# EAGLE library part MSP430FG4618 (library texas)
MIXED SIGNAL MICROCONTROLLER Auto generated by make-symbol-device-package-bsdl.ulp Rev. 19 Source: http://focus.ti.com/docs/prod/folders/print/msp430fg4618.html
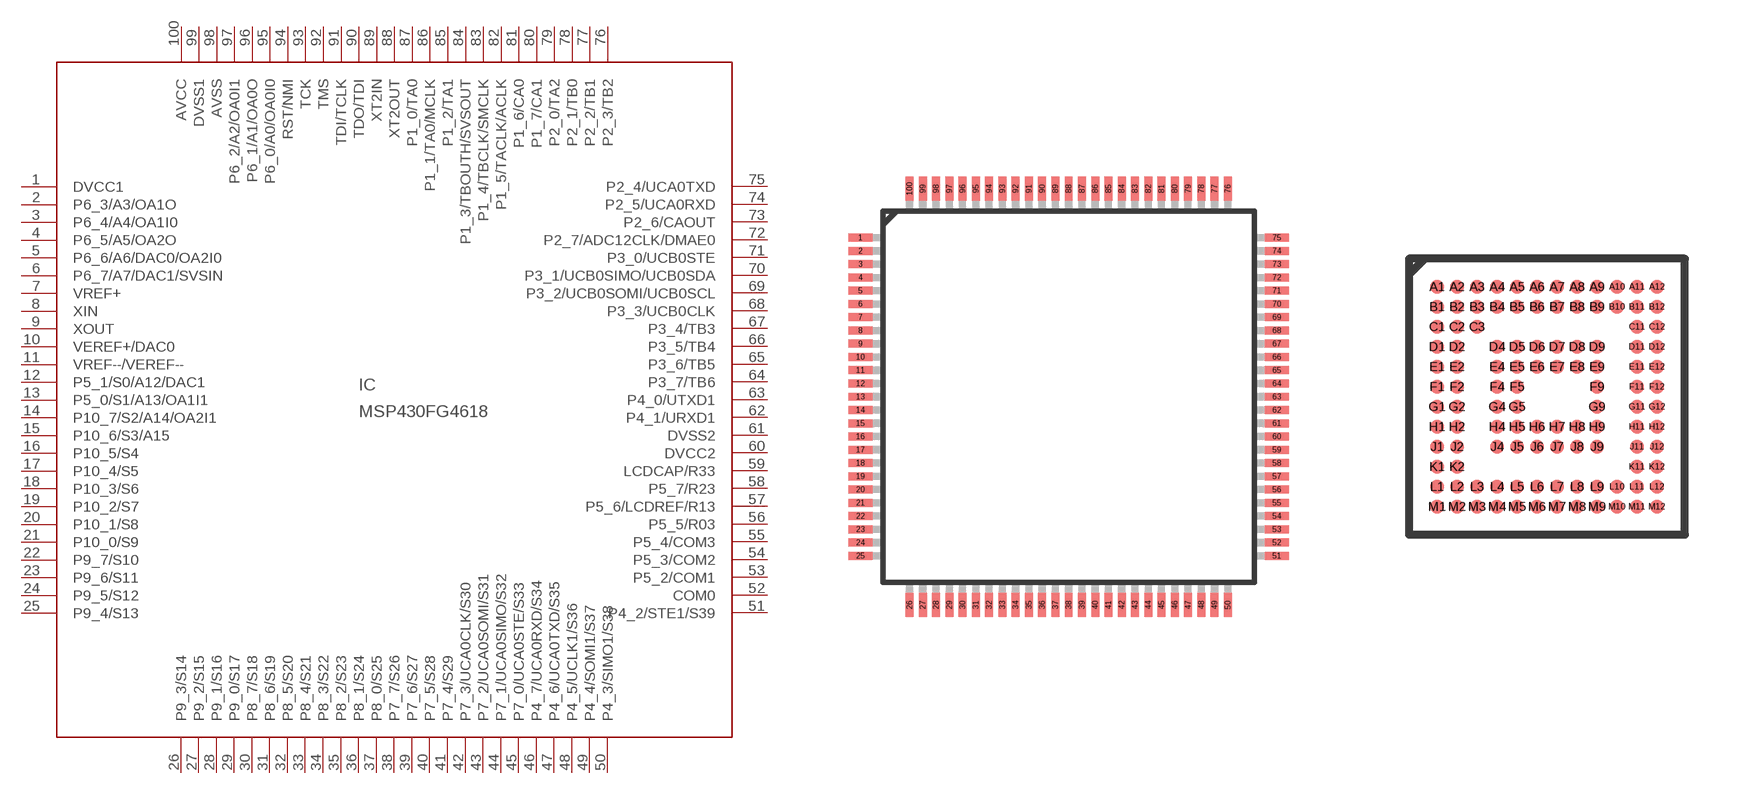
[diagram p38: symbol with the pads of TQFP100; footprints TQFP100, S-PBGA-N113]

Designator prefix IC

## MSP430FG4618PZ (MPN: MSP430FG4618IPZ; OC_FARNELL: 1470488; OC_NEWARK: 22M1151)  [TQFP100]
1  DVCC1  pwr
2  P6_3/A3/OA1O
3  P6_4/A4/OA1I0
4  P6_5/A5/OA2O
5  P6_6/A6/DAC0/OA2I0
6  P6_7/A7/DAC1/SVSIN
7  VREF+  out
8  XIN  in
9  XOUT  out
10  VEREF+/DAC0
11  VREF--/VEREF--  in
12  P5_1/S0/A12/DAC1
13  P5_0/S1/A13/OA1I1
14  P10_7/S2/A14/OA2I1
15  P10_6/S3/A15
16  P10_5/S4
17  P10_4/S5
18  P10_3/S6
19  P10_2/S7
20  P10_1/S8
21  P10_0/S9
22  P9_7/S10
23  P9_6/S11
24  P9_5/S12
25  P9_4/S13
26  P9_3/S14
27  P9_2/S15
28  P9_1/S16
29  P9_0/S17
30  P8_7/S18
31  P8_6/S19
32  P8_5/S20
33  P8_4/S21
34  P8_3/S22
35  P8_2/S23
36  P8_1/S24
37  P8_0/S25
38  P7_7/S26
39  P7_6/S27
40  P7_5/S28
41  P7_4/S29
42  P7_3/UCA0CLK/S30
43  P7_2/UCA0SOMI/S31
44  P7_1/UCA0SIMO/S32
45  P7_0/UCA0STE/S33
46  P4_7/UCA0RXD/S34
47  P4_6/UCA0TXD/S35
48  P4_5/UCLK1/S36
49  P4_4/SOMI1/S37
50  P4_3/SIMO1/S38
51  P4_2/STE1/S39
52  COM0  out
53  P5_2/COM1
54  P5_3/COM2
55  P5_4/COM3
56  P5_5/R03
57  P5_6/LCDREF/R13
58  P5_7/R23
59  LCDCAP/R33  in
60  DVCC2  pwr
61  DVSS2  pwr
62  P4_1/URXD1
63  P4_0/UTXD1
64  P3_7/TB6
65  P3_6/TB5
66  P3_5/TB4
67  P3_4/TB3
68  P3_3/UCB0CLK
69  P3_2/UCB0SOMI/UCB0SCL
70  P3_1/UCB0SIMO/UCB0SDA
71  P3_0/UCB0STE
72  P2_7/ADC12CLK/DMAE0
73  P2_6/CAOUT
74  P2_5/UCA0RXD
75  P2_4/UCA0TXD
76  P2_3/TB2
77  P2_2/TB1
78  P2_1/TB0
79  P2_0/TA2
80  P1_7/CA1
81  P1_6/CA0
82  P1_5/TACLK/ACLK
83  P1_4/TBCLK/SMCLK
84  P1_3/TBOUTH/SVSOUT
85  P1_2/TA1
86  P1_1/TA0/MCLK
87  P1_0/TA0
88  XT2OUT  out
89  XT2IN  in
90  TDO/TDI
91  TDI/TCLK  in
92  TMS  in
93  TCK  in
94  RST/NMI  in
95  P6_0/A0/OA0I0
96  P6_1/A1/OA0O
97  P6_2/A2/OA0I1
98  AVSS  pwr
99  DVSS1  pwr
100  AVCC  pwr

## MSP430FG4618ZQW (MPN: MSP430FG4618IZQW; OC_FARNELL: unknown; OC_NEWARK: 61M7852)  [S-PBGA-N113]
A1  DVCC1  pwr
A2  AVCC  pwr
A3  AVSS  pwr
A4  P6_0/A0/OA0I0
A5  TCK  in
A6  TDO/TDI
A7  P1_0/TA0
A8  P1_3/TBOUTH/SVSOUT
A9  P1_6/CA0
A10  P2_0/TA2
A11  P2_3/TB2
B1  P6_3/A3/OA1O
B2  P6_4/A4/OA1I0
B3  DVSS1  pwr
B4  P6_2/A2/OA0I1
B5  RST/NMI  in
B6  XT2IN  in
B7  XT2OUT  out
B8  P1_4/TBCLK/SMCLK
B9  P1_5/TACLK/ACLK
B10  P1_7/CA1
B12  P2_4/UCA0TXD
C1  P6_6/A6/DAC0/OA2I0
C2  P6_5/A5/OA2O
C3  P6_7/A7/DAC1/SVSIN
C11  P2_5/UCA0RXD
C12  P2_6/CAOUT
D1  XIN  in
D2  VREF+  out
D5  P6_1/A1/OA0O
D6  TDI/TCLK  in
D7  P1_2/TA1
D8  P2_1/TB0
D11  P3_0/UCB0STE
D12  P3_1/UCB0SIMO/UCB0SDA
E1  XOUT  out
E2  VEREF+/DAC0
E4  VREF--/VEREF--  in
E5  P10_7/S2/A14/OA2I1
E6  TMS  in
E7  P1_1/TA0/MCLK
E8  P2_2/TB1
E9  P2_7/ADC12CLK/DMAE0
E11  P3_3/UCB0CLK
E12  P3_4/TB3
F1  P5_1/S0/A12/DAC1
F2  P5_0/S1/A13/OA1I1
F4  P10_4/S5
F5  P10_1/S8
F9  P3_2/UCB0SOMI/UCB0SCL
F11  P3_6/TB5
F12  P3_7/TB6
G1  P10_6/S3/A15
G2  P10_5/S4
G4  P9_6/S11
G5  P8_4/S21
G9  P3_5/TB4
G11  P4_1/URXD1
G12  DVSS2  pwr
H1  P10_3/S6
H2  P10_2/S7
H4  P8_7/S18
H5  P8_1/S24
H6  P7_3/UCA0CLK/S30
H7  P4_4/SOMI1/S37
H9  P4_0/UTXD1
H11  LCDCAP/R33  in
H12  DVCC2  pwr
J1  P10_0/S9
J2  P9_7/S10
J5  P8_0/S25
J6  P7_5/S28
J7  P4_7/UCA0RXD/S34
J8  P5_3/COM2
J11  P5_7/R23
J12  P5_6/LCDREF/R13
K1  P9_5/S12
K2  P9_2/S15
K11  P5_5/R03
K12  P5_4/COM3
L1  P9_4/S13
L3  P9_1/S16
L4  P8_6/S19
L5  P8_3/S22
L6  P7_6/S27
L7  P7_2/UCA0SOMI/S31
L8  P7_0/UCA0STE/S33
L9  P4_5/UCLK1/S36
L10  COM0  out
L12  P5_2/COM1
M2  P9_3/S14
M3  P9_0/S17
M4  P8_5/S20
M5  P8_2/S23
M6  P7_7/S26
M7  P7_4/S29
M8  P7_1/UCA0SIMO/S32
M9  P4_6/UCA0TXD/S35
M10  P4_3/SIMO1/S38
M11  P4_2/STE1/S39

## Footprint TQFP100 (pad centres in mm)
PLASTIC 100-PIN TQFP (PZ) Auto generated by make-symbol-device-package-bsdl.ulp Rev. 19 Source: http://focus.ti.com/docs/prod/folders/print/msp430fg4618.html
smd 0.9 x 0.3: 1 -7.85,6; 2 -7.85,5.5; 3 -7.85,5; 4 -7.85,4.5; 5 -7.85,4; 6 -7.85,3.5; 7 -7.85,3; 8 -7.85,2.5; 9 -7.85,2; 10 -7.85,1.5; 11 -7.85,1; 12 -7.85,0.5; 13 -7.85,0; 14 -7.85,-0.5; 15 -7.85,-1; 16 -7.85,-1.5; 17 -7.85,-2; 18 -7.85,-2.5; 19 -7.85,-3; 20 -7.85,-3.5; 21 -7.85,-4; 22 -7.85,-4.5; 23 -7.85,-5; 24 -7.85,-5.5; 25 -7.85,-6; 51 7.85,-6; 52 7.85,-5.5; 53 7.85,-5; 54 7.85,-4.5; 55 7.85,-4; 56 7.85,-3.5; 57 7.85,-3; 58 7.85,-2.5; 59 7.85,-2; 60 7.85,-1.5; 61 7.85,-1; 62 7.85,-0.5; 63 7.85,0; 64 7.85,0.5; 65 7.85,1; 66 7.85,1.5; 67 7.85,2; 68 7.85,2.5; 69 7.85,3; 70 7.85,3.5; 71 7.85,4; 72 7.85,4.5; 73 7.85,5; 74 7.85,5.5; 75 7.85,6
smd 0.3 x 0.9: 26 -6,-7.85; 27 -5.5,-7.85; 28 -5,-7.85; 29 -4.5,-7.85; 30 -4,-7.85; 31 -3.5,-7.85; 32 -3,-7.85; 33 -2.5,-7.85; 34 -2,-7.85; 35 -1.5,-7.85; 36 -1,-7.85; 37 -0.5,-7.85; 38 0,-7.85; 39 0.5,-7.85; 40 1,-7.85; 41 1.5,-7.85; 42 2,-7.85; 43 2.5,-7.85; 44 3,-7.85; 45 3.5,-7.85; 46 4,-7.85; 47 4.5,-7.85; 48 5,-7.85; 49 5.5,-7.85; 50 6,-7.85; 76 6,7.85; 77 5.5,7.85; 78 5,7.85; 79 4.5,7.85; 80 4,7.85; 81 3.5,7.85; 82 3,7.85; 83 2.5,7.85; 84 2,7.85; 85 1.5,7.85; 86 1,7.85; 87 0.5,7.85; 88 0,7.85; 89 -0.5,7.85; 90 -1,7.85; 91 -1.5,7.85; 92 -2,7.85; 93 -2.5,7.85; 94 -3,7.85; 95 -3.5,7.85; 96 -4,7.85; 97 -4.5,7.85; 98 -5,7.85; 99 -5.5,7.85; 100 -6,7.85

## Footprint S-PBGA-N113 (pad centres in mm)
PLASTIC BGA 113-BALL (ZQW) Auto generated by make-symbol-device-package-bsdl.ulp Rev. 19 Source: http://focus.ti.com/docs/prod/folders/print/msp430fg4618.html
smd 0.35 x 0.35: A1 -2.75,2.75; A2 -2.25,2.75; A3 -1.75,2.75; A4 -1.25,2.75; A5 -0.75,2.75; A6 -0.25,2.75; A7 0.25,2.75; A8 0.75,2.75; A9 1.25,2.75; A10 1.75,2.75; A11 2.25,2.75; A12 2.75,2.75; B1 -2.75,2.25; B2 -2.25,2.25; B3 -1.75,2.25; B4 -1.25,2.25; B5 -0.75,2.25; B6 -0.25,2.25; B7 0.25,2.25; B8 0.75,2.25; B9 1.25,2.25; B10 1.75,2.25; B11 2.25,2.25; B12 2.75,2.25; C1 -2.75,1.75; C2 -2.25,1.75; C3 -1.75,1.75; C11 2.25,1.75; C12 2.75,1.75; D1 -2.75,1.25; D2 -2.25,1.25; D4 -1.25,1.25; D5 -0.75,1.25; D6 -0.25,1.25; D7 0.25,1.25; D8 0.75,1.25; D9 1.25,1.25; D11 2.25,1.25; D12 2.75,1.25; E1 -2.75,0.75; E2 -2.25,0.75; E4 -1.25,0.75; E5 -0.75,0.75; E6 -0.25,0.75; E7 0.25,0.75; E8 0.75,0.75; E9 1.25,0.75; E11 2.25,0.75; E12 2.75,0.75; F1 -2.75,0.25; F2 -2.25,0.25; F4 -1.25,0.25; F5 -0.75,0.25; F9 1.25,0.25; F11 2.25,0.25; F12 2.75,0.25; G1 -2.75,-0.25; G2 -2.25,-0.25; G4 -1.25,-0.25; G5 -0.75,-0.25; G9 1.25,-0.25; G11 2.25,-0.25; G12 2.75,-0.25; H1 -2.75,-0.75; H2 -2.25,-0.75; H4 -1.25,-0.75; H5 -0.75,-0.75; H6 -0.25,-0.75; H7 0.25,-0.75; H8 0.75,-0.75; H9 1.25,-0.75; H11 2.25,-0.75; H12 2.75,-0.75; J1 -2.75,-1.25; J2 -2.25,-1.25; J4 -1.25,-1.25; J5 -0.75,-1.25; J6 -0.25,-1.25; J7 0.25,-1.25; J8 0.75,-1.25; J9 1.25,-1.25; J11 2.25,-1.25; J12 2.75,-1.25; K1 -2.75,-1.75; K2 -2.25,-1.75; K11 2.25,-1.75; K12 2.75,-1.75; L1 -2.75,-2.25; L2 -2.25,-2.25; L3 -1.75,-2.25; L4 -1.25,-2.25; L5 -0.75,-2.25; L6 -0.25,-2.25; L7 0.25,-2.25; L8 0.75,-2.25; L9 1.25,-2.25; L10 1.75,-2.25; L11 2.25,-2.25; L12 2.75,-2.25; M1 -2.75,-2.75; M2 -2.25,-2.75; M3 -1.75,-2.75; M4 -1.25,-2.75; M5 -0.75,-2.75; M6 -0.25,-2.75; M7 0.25,-2.75; M8 0.75,-2.75; M9 1.25,-2.75; M10 1.75,-2.75; M11 2.25,-2.75; M12 2.75,-2.75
